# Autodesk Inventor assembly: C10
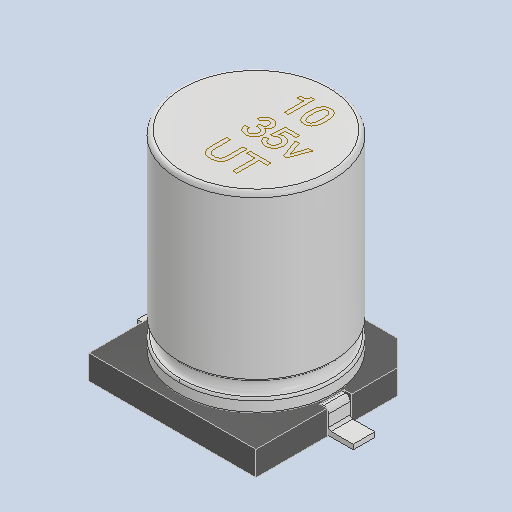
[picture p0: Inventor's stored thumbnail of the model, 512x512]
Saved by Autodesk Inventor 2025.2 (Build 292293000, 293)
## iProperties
Created: 2025-04
Part Number: C10
Description: PART--DESC
Document SubType Name: Assembly
Designer: BennF
Author: BennF
Revision Number: NONE
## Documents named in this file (4)
- C:\Users\BennF\Nextcloud\Benutzer\CNC JarBeRi\existing parts\Electronics\RepRap A4988 Shied (USE WITHOUT ARDUINO)\reprap-a4988-1.snapshot.1\RepRap\RepRap\C10_1.iam
- C:\Users\BennF\Nextcloud\Benutzer\CNC JarBeRi\existing parts\Electronics\RepRap A4988 Shied (USE WITHOUT ARDUINO)\reprap-a4988-1.snapshot.1\RepRap\RepRap\C10 Geometry.ipt
- C:\Users\BennF\Nextcloud\Benutzer\CNC JarBeRi\existing parts\Electronics\RepRap A4988 Shied (USE WITHOUT ARDUINO)\reprap-a4988-1.snapshot.1\RepRap\RepRap\bay2_1.iam
- C:\Users\BennF\Nextcloud\Benutzer\CNC JarBeRi\existing parts\Electronics\RepRap A4988 Shied (USE WITHOUT ARDUINO)\reprap-a4988-1.snapshot.1\RepRap\RepRap\name4.ipt
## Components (3 placed, 3 different names)
1. C10 Geometry
2. bay2 [sub-assembly]
3. name4
